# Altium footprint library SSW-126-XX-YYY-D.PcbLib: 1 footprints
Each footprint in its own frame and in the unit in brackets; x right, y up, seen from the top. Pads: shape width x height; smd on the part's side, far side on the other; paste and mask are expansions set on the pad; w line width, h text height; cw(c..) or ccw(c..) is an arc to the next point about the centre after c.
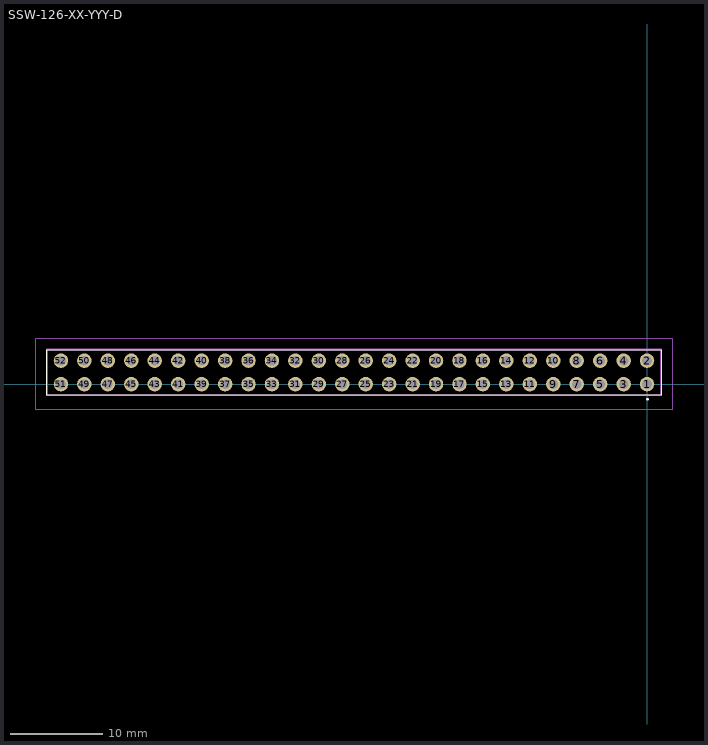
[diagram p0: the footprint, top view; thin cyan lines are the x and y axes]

## SSW-126-XX-YYY-D [mm]
pads (52):
  round 1.57 hole 1.04: 1(0,0) 2(0,2.54) 3(-2.54,0) 4(-2.54,2.54) 5(-5.08,0) 6(-5.08,2.54) 7(-7.62,0) 8(-7.62,2.54) 9(-10.16,0) 10(-10.16,2.54) 11(-12.7,0) 12(-12.7,2.54) 13(-15.24,0) 14(-15.24,2.54) 15(-17.78,0) 16(-17.78,2.54) 17(-20.32,0) 18(-20.32,2.54) 19(-22.86,0) 20(-22.86,2.54) 21(-25.4,0) 22(-25.4,2.54) 23(-27.94,0) 24(-27.94,2.54) 25(-30.48,0) 26(-30.48,2.54) 27(-33.02,0) 28(-33.02,2.54) 29(-35.56,0) 30(-35.56,2.54) 31(-38.1,0) 32(-38.1,2.54) 33(-40.64,0) 34(-40.64,2.54) 35(-43.18,0) 36(-43.18,2.54) 37(-45.72,0) 38(-45.72,2.54) 39(-48.26,0) 40(-48.26,2.54) 41(-50.8,0) 42(-50.8,2.54) 43(-53.34,0) 44(-53.34,2.54) 45(-55.88,0) 46(-55.88,2.54) 47(-58.42,0) 48(-58.42,2.54) 49(-60.96,0) 50(-60.96,2.54) 51(-63.5,0) 52(-63.5,2.54)
Top Overlay:
  circle w0.2: c0.05,-1.65 r0.05
  lines w0.1: -65.025,-1.205 1.525,-1.205 1.525,3.745 -65.025,3.745 -65.025,-1.205
Mechanical 15:
  lines w0.2: -65.025,-1.205 1.525,-1.205 1.525,3.745 -65.025,3.745 -65.025,-1.205
Mechanical 20:
  lines w0.05: -66.225,-2.75 2.725,-2.75 2.725,4.945 -66.225,4.945 -66.225,-2.75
